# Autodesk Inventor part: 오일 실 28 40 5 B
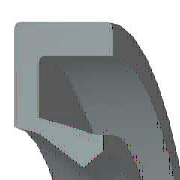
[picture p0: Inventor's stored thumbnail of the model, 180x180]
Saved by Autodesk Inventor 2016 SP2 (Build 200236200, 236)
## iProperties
IsCustomPart: 1
Created: 2012-02
Part Number: 오일 실 28 40 5 B
Material: 고무
Description: 오일 실 - 비스프링, 조립 GA
Document SubType Name: Modeling
Standard: JIS B 2402
Designer: mduedu
Standards Organization: JIS
Language: ko-KR
Size Designation: 28 40 5 B
Categories: <MemberInstance><Categories><Category DisplayName="샤프트 부품" InternalName="7f7aeb1f-a693-4053-b835-cee3144e0d98" Mnemonic="SHFT"><Category DisplayName="실링" Intern
Density: 0.93 g/cm^3
Appearance: Rubber-Black
Author: mduedu
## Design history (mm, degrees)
body "Solid1"
revolve "회전1" stored, may be unused: angle "d27" = 360 deg
fillet "모깎기1" dims "d28" = 0.25 (= 0.05 x b)
sketch "스케치2"
  geometry: L1 (15.971, -3.75)-(16.571, -5); L2 (15.171, -3.438)-(15.971, -3.75); L3 (14, -1.375)-(15.171, -3.438); L4 (14.923, -0.75)-(14, -1.375); L5 (17.6, -4.375)-(14.923, -0.75); L6 (17.6, -0.25)-(17.6, -4.375); L7 (18.8, -0.25)-(17.6, -0.25); L8 (18.8, 0)-(18.8, -0.25); L9 (20, 0)-(18.8, 0); L10 (20, -5)-(20, 0); L11 (16.571, -5)-(20, -5); L12 (0, -9.6)-(0, 1.6) reference; L13 (28, 0)-(14, 0) reference
  constraints: 22 end point, 3 horizontal, 3 vertical
  dimensions: "d2" = 5 distance of L10.start L9.start (= b); "d4" = 1.2 distance of L9.start L8.start (= 0.1 x dd - 0.1 x Diam); "d6" = 0.25 distance of L8.start L7.start (= 0.05 x b); "d8" = 0.92308 horizontal distance of L4.start L3.start (= 0.0769231 x dd - 0.0769231 x Diam); "d10" = 0.625 vertical distance of L5.start L10.start (= 0.125 x b); "d12" = 1.2 distance of L7.start L6.start (= 0.1 x dd - 0.1 x Diam); "d14" = 0.5 vertical distance of L4.start L6.start (= 0.1 x b); "d16" = 3.42857 distance of L1.end L10.start (= 0.285714 x dd - 0.285714 x Diam); "d18" = 0.6 horizontal distance of L1.start L1.end (= 0.05 x dd - 0.05 x Diam); "d20" = 0.625 vertical distance of L4.start L3.start (= 0.125 x b); "d22" = 1.25 vertical distance of L1.start L1.end (= 0.25 x b); "d24" = 0.8 horizontal distance of L2.start L1.start (= 0.0666667 x dd - 0.0666667 x Diam); "d26" = 0.3125 vertical distance of L2.start L1.start (= 0.0625 x b); "d29" = 0 distance between parallel lines of L13 L9; "d30" = 14 distance from line of L3.start L12 (= 0.5 x Diam); "d31" = 20 distance between parallel lines of L12 L10 (= 0.5 x dd)
other parameters: "Diam" = 28 [user parameter; used in 7 equation terms], "b" = 5 [user parameter; used in 8 equation terms], "d1" = 8 (derived), "d3" = 2 (derived), "d5" = 0.4 (derived), "d7" = 1.53846 (derived), "d9" = 1 (derived), "d11" = 2 (derived), "d13" = 0.8 (derived), "d15" = 5.71429 (derived), "d17" = 1 (derived), "d19" = 1 (derived), "d21" = 2 (derived), "d23" = 1.33333 (derived), "d25" = 0.5 (derived), "d32" = 0
